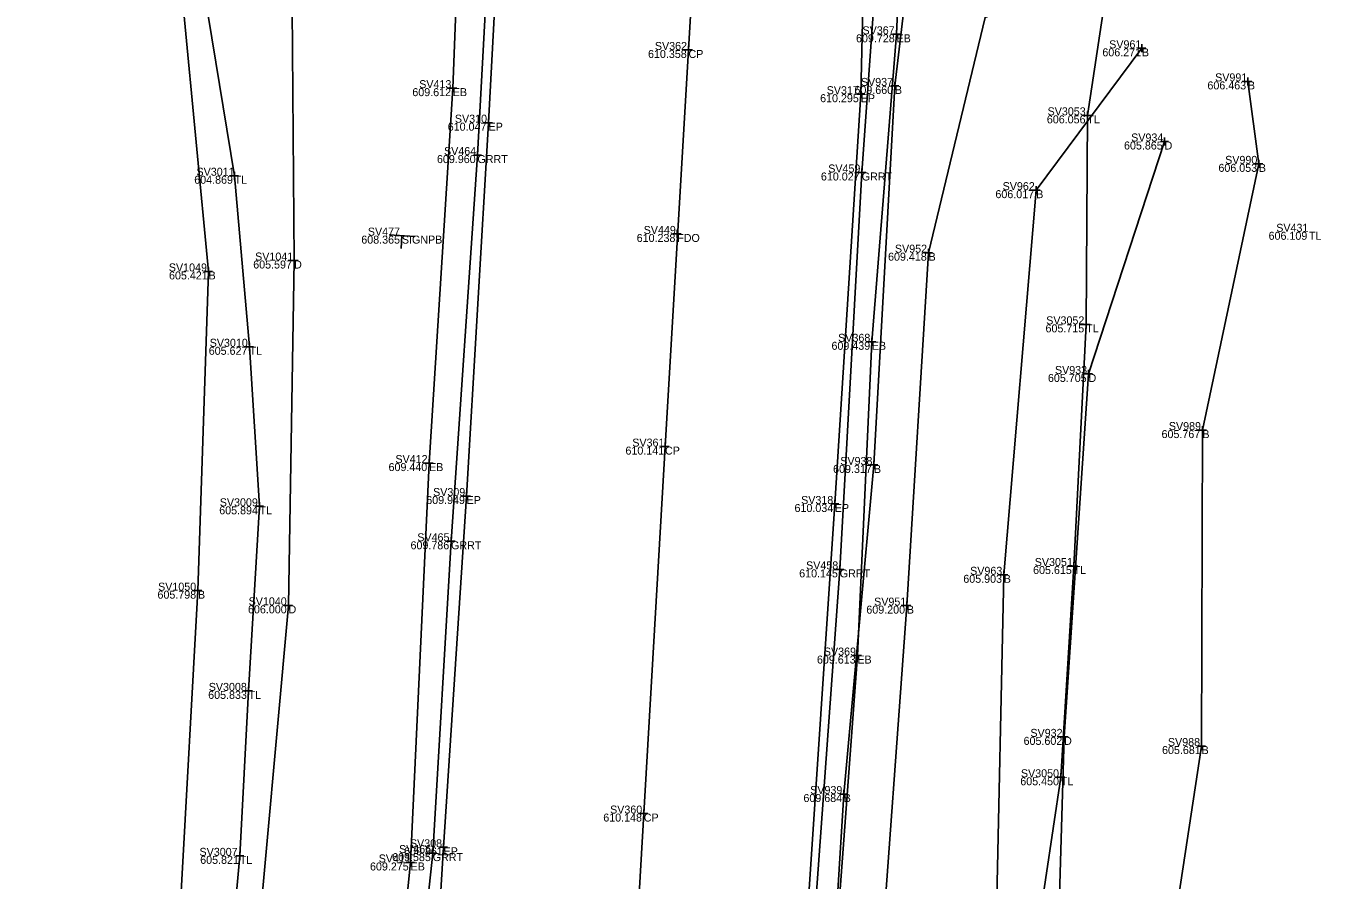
# Model space of a CAD drawing. Extents: x -2 to 1979875, y -2 to 232027.
# Drawn here: x 1978730.2 to 1978811.1, y 231153.6 to 231206.9 of the extents above; entities that cross this region are included whole.
import ezdxf

# ---------------------------------------------------------------- set-up
doc = ezdxf.new("R2010")
doc.units = 0
for name, color, linetype in [('_CIVIL_CONSTRUCTION', 7, 'Continuous'), ('DR_X_Ditch', 7, 'Continuous'), ('GE_P_Alignment', 7, 'Continuous'), ('GE_P_Alignment_1000_Curve_Data', 7, 'Continuous'), ('GE_P_Alignment_1000_Stations', 7, 'Continuous'), ('GE_P_Alignment_500_Curve_Data', 7, 'Continuous'), ('GE_X_Alignment', 7, 'Continuous'), ('GE_X_Alignment_1000_Curve_Data', 7, 'Continuous'), ('GE_X_Alignment_1000_Stations', 7, 'Continuous'), ('GE_X_Alignment_100_Curve_Data', 7, 'Continuous'), ('GE_X_Alignment_100_Stations', 7, 'Continuous'), ('GE_X_Alignment_500_Stations', 7, 'Continuous'), ('SC_Scratch1', 7, 'Continuous')]:
    doc.layers.add(name, color=color, linetype=linetype)

msp = doc.modelspace()

# ---------------------------------------------------------------- linework, layer by layer
at = {"layer": 'DR_X_Ditch'}
for points in [[(1978742.253, 231123.729), (1978744.469, 231147.505), (1978746.577, 231170.723), (1978746.925, 231192.27), (1978746.813, 231208.011), (1978745.79, 231216.793), (1978746.707, 231228.131), (1978745.697, 231237.66), (1978746.077, 231246.913)], [(1978769.61, 230735.533), (1978764.556, 230757.762), (1978761.888, 230780.52), (1978761.255, 230802.491), (1978762.758, 230825.129), (1978765.137, 230850.029), (1978768.569, 230875.252), (1978770.473, 230901.75), (1978772.394, 230926.88), (1978774.225, 230946.118), (1978776.188, 230970.1), (1978776.947, 230991.277), (1978778.808, 231013.722), (1978780.679, 231036.008), (1978780.852, 231047.689), (1978785.42, 231078.945), (1978790.697, 231097.051), (1978792.307, 231119.545), (1978794.395, 231141.248), (1978795.023, 231162.503), (1978796.552, 231185.182), (1978801.304, 231199.708)]]:
    msp.add_lwpolyline(points, dxfattribs=at)
at = {"layer": 'GE_P_Alignment'}
for points in [[(1978788.119, 231249.408), (1978786.943, 231224.352), (1978784.459, 231203.181), (1978783.148, 231179.495), (1978781.259, 231158.933), (1978779.831, 231135.814), (1978779.399, 231114.976), (1978780.51, 231101.208), (1978780.469, 231098.542), (1978778.925, 231080.086), (1978777.811, 231054.63), (1978776.389, 231030.876)], [(1978782.883, 231095.387), (1978784.018, 231105.569), (1978783.215, 231126.435), (1978783.474, 231146.96), (1978785.203, 231170.705), (1978786.559, 231192.76), (1978790.09, 231207.457), (1978796.435, 231210.256), (1978800.205, 231220.321), (1978799.997, 231235.458), (1978797.94, 231243.541), (1978796.315, 231248.532)], [(1978742.352, 231226.722), (1978740.039, 231207.756), (1978741.585, 231191.589), (1978740.923, 231171.641), (1978739.848, 231152.451), (1978736.877, 231135.037), (1978737.12, 231125.328)], [(1978799.886, 231205.531), (1978793.286, 231196.667), (1978791.255, 231172.632), (1978790.773, 231150.51), (1978789.185, 231127.08), (1978788.834, 231106.775), (1978786.415, 231093.172)], [(1978769.951, 230803.3), (1978770.804, 230818.73), (1978769.172, 230825.121), (1978771.54, 230837.858), (1978774.593, 230856.702), (1978777.309, 230875.323), (1978778.206, 230900.393), (1978780.194, 230917.861), (1978782.495, 230932.89), (1978782.493, 230947.115), (1978785.767, 230964.209), (1978787.856, 230986.866), (1978787.326, 231009.356), (1978787.324, 231025.342), (1978791.304, 231037.316), (1978793.971, 231062.015), (1978792.008, 231077.675), (1978794.496, 231103.739), (1978796.727, 231125.192), (1978800.775, 231143.28), (1978803.614, 231161.931), (1978803.663, 231181.675), (1978807.191, 231198.311), (1978806.504, 231203.464)]]:
    msp.add_lwpolyline(points, dxfattribs=at)
at = {"layer": 'GE_P_Alignment_1000_Curve_Data'}
for points in [[(1978791.661, 231060.333), (1978792.296, 231074.691), (1978791.754, 231088.963), (1978792.43, 231104.517), (1978792.032, 231117.838), (1978792.133, 231132.395), (1978792.905, 231147.152), (1978794.82, 231159.979), (1978795.624, 231173.18), (1978796.399, 231188.281), (1978796.48, 231201.342), (1978798.136, 231212.257), (1978799.055, 231226.533), (1978800.349, 231239.171), (1978800.253, 231250.204), (1978805.284, 231291.391)], [(1978737.693, 231077.945), (1978737.389, 231087.473), (1978737.815, 231097.725), (1978739.016, 231107.053), (1978740.421, 231120.833), (1978741.632, 231130.981), (1978742.549, 231144.249), (1978743.532, 231155.069), (1978744.086, 231165.377), (1978744.766, 231176.911), (1978744.147, 231186.88), (1978743.211, 231197.568), (1978741.558, 231207.59), (1978737.988, 231217.051), (1978732.124, 231225.954), (1978730.174, 231231.053), (1978733.125, 231254.651), (1978737.318, 231281.706)]]:
    msp.add_lwpolyline(points, dxfattribs=at)
at = {"layer": 'GE_P_Alignment_1000_Stations'}
for points in [[(1978761.115, 231248.004), (1978759.735, 231223.843), (1978758.381, 231198.86), (1978756.732, 231174.726), (1978755.587, 231155.241), (1978753.463, 231135.535), (1978751.71, 231124.03)], [(1978779.18, 231099.769), (1978777.975, 231123.065), (1978779.192, 231147.605), (1978781.012, 231172.97), (1978782.386, 231197.771), (1978784.253, 231223.721), (1978785.562, 231247.078)]]:
    msp.add_lwpolyline(points, dxfattribs=at)
at = {"layer": 'GE_P_Alignment_500_Curve_Data'}
for p, q in [((1978770.608, 231193.931), (1978771.108, 231193.931)), ((1978770.858, 231194.181), (1978770.858, 231193.681)), ((1978770.858, 231193.931), (1978770.858, 231193.931))]:
    msp.add_line(p, q, dxfattribs=at)
at = {"layer": 'GE_X_Alignment_1000_Curve_Data'}
msp.add_lwpolyline([(1978759.598, 230998.872), (1978761.121, 231023.464), (1978762.432, 231045.872), (1978763.634, 231067.205), (1978765.062, 231090.264), (1978766.176, 231112.831), (1978767.489, 231135.467), (1978768.77, 231157.711), (1978770.096, 231180.642), (1978771.565, 231205.428), (1978772.87, 231227.762), (1978774.351, 231252.439)], dxfattribs=at)
at = {"layer": 'GE_X_Alignment_1000_Stations'}
for points in [[(1978748.464, 231019.612), (1978749.988, 231043.472), (1978751.447, 231065.273), (1978752.63, 231084.658), (1978753.33, 231098.021), (1978753.711, 231111.371), (1978754.899, 231133.583), (1978756.265, 231155.604), (1978757.703, 231177.553), (1978759.075, 231200.883), (1978760.359, 231225.015), (1978761.255, 231242.617), (1978761.827, 231253.108)], [(1978785.568, 231251.827), (1978784.19, 231242.096), (1978782.784, 231222.648), (1978782.32, 231202.663), (1978780.702, 231177.057), (1978778.946, 231150.803), (1978777.805, 231126.797), (1978776.986, 231106.931), (1978775.705, 231085.257), (1978774.572, 231063.753), (1978773.517, 231041.76), (1978772.029, 231016.51), (1978770.7, 230994.507), (1978769.257, 230972.092), (1978767.73, 230948.595), (1978766.192, 230924.232), (1978764.603, 230899.039), (1978762.827, 230873.547), (1978761.273, 230848.668), (1978759.848, 230822.744), (1978759.345, 230799.915), (1978760.114, 230777.862), (1978762.938, 230755.551), (1978769.839, 230729.514)]]:
    msp.add_lwpolyline(points, dxfattribs=at)
at = {"layer": 'GE_X_Alignment_100_Curve_Data'}
for p, q in [((1978784.558, 231206.657), (1978784.558, 231206.157)), ((1978771.565, 231205.678), (1978771.565, 231205.178)), ((1978784.308, 231206.407), (1978784.808, 231206.407)), ((1978784.558, 231206.407), (1978784.558, 231206.407)), ((1978799.886, 231205.781), (1978799.886, 231205.281)), ((1978771.315, 231205.428), (1978771.815, 231205.428)), ((1978771.565, 231205.428), (1978771.565, 231205.428)), ((1978799.636, 231205.531), (1978800.136, 231205.531)), ((1978799.886, 231205.531), (1978799.886, 231205.531)), ((1978756.841, 231203.291), (1978756.841, 231202.791)), ((1978784.459, 231203.431), (1978784.459, 231202.931)), ((1978806.254, 231203.464), (1978806.754, 231203.464)), ((1978806.504, 231203.714), (1978806.504, 231203.214)), ((1978806.504, 231203.464), (1978806.504, 231203.464)), ((1978756.591, 231203.041), (1978757.091, 231203.041)), ((1978756.841, 231203.041), (1978756.841, 231203.041)), ((1978782.07, 231202.663), (1978782.57, 231202.663)), ((1978782.32, 231202.913), (1978782.32, 231202.413)), ((1978782.32, 231202.663), (1978782.32, 231202.663)), ((1978784.209, 231203.181), (1978784.709, 231203.181)), ((1978784.459, 231203.181), (1978784.459, 231203.181)), ((1978758.825, 231200.883), (1978759.325, 231200.883)), ((1978759.075, 231201.133), (1978759.075, 231200.633)), ((1978759.075, 231200.883), (1978759.075, 231200.883)), ((1978796.23, 231201.342), (1978796.73, 231201.342)), ((1978796.48, 231201.592), (1978796.48, 231201.092)), ((1978796.48, 231201.342), (1978796.48, 231201.342)), ((1978801.054, 231199.708), (1978801.554, 231199.708)), ((1978801.304, 231199.958), (1978801.304, 231199.458)), ((1978801.304, 231199.708), (1978801.304, 231199.708)), ((1978758.131, 231198.86), (1978758.631, 231198.86)), ((1978758.381, 231199.11), (1978758.381, 231198.61)), ((1978758.381, 231198.86), (1978758.381, 231198.86)), ((1978807.191, 231198.561), (1978807.191, 231198.061)), ((1978742.961, 231197.568), (1978743.461, 231197.568)), ((1978743.211, 231197.818), (1978743.211, 231197.318)), ((1978743.211, 231197.568), (1978743.211, 231197.568)), ((1978782.136, 231197.771), (1978782.636, 231197.771)), ((1978782.386, 231198.021), (1978782.386, 231197.521)), ((1978782.386, 231197.771), (1978782.386, 231197.771)), ((1978806.941, 231198.311), (1978807.441, 231198.311)), ((1978807.191, 231198.311), (1978807.191, 231198.311)), ((1978793.286, 231196.917), (1978793.286, 231196.417)), ((1978793.036, 231196.667), (1978793.536, 231196.667)), ((1978793.286, 231196.667), (1978793.286, 231196.667)), ((1978786.309, 231192.76), (1978786.809, 231192.76)), ((1978786.559, 231193.01), (1978786.559, 231192.51)), ((1978786.559, 231192.76), (1978786.559, 231192.76)), ((1978746.675, 231192.27), (1978747.175, 231192.27)), ((1978746.925, 231192.52), (1978746.925, 231192.02)), ((1978746.925, 231192.27), (1978746.925, 231192.27)), ((1978741.335, 231191.589), (1978741.835, 231191.589)), ((1978741.585, 231191.839), (1978741.585, 231191.339)), ((1978741.585, 231191.589), (1978741.585, 231191.589)), ((1978796.149, 231188.281), (1978796.649, 231188.281)), ((1978796.399, 231188.531), (1978796.399, 231188.031)), ((1978796.399, 231188.281), (1978796.399, 231188.281)), ((1978744.147, 231187.13), (1978744.147, 231186.63)), ((1978782.766, 231187.193), (1978783.266, 231187.193)), ((1978783.016, 231187.443), (1978783.016, 231186.943)), ((1978783.016, 231187.193), (1978783.016, 231187.193)), ((1978743.897, 231186.88), (1978744.397, 231186.88)), ((1978744.147, 231186.88), (1978744.147, 231186.88)), ((1978796.552, 231185.432), (1978796.552, 231184.932)), ((1978796.302, 231185.182), (1978796.802, 231185.182)), ((1978796.552, 231185.182), (1978796.552, 231185.182)), ((1978803.413, 231181.675), (1978803.913, 231181.675)), ((1978803.663, 231181.925), (1978803.663, 231181.425)), ((1978803.663, 231181.675), (1978803.663, 231181.675)), ((1978769.846, 231180.642), (1978770.346, 231180.642)), ((1978770.096, 231180.892), (1978770.096, 231180.392)), ((1978770.096, 231180.642), (1978770.096, 231180.642)), ((1978755.357, 231179.863), (1978755.357, 231179.363)), ((1978755.107, 231179.613), (1978755.607, 231179.613)), ((1978755.357, 231179.613), (1978755.357, 231179.613)), ((1978782.898, 231179.495), (1978783.398, 231179.495)), ((1978783.148, 231179.745), (1978783.148, 231179.245)), ((1978783.148, 231179.495), (1978783.148, 231179.495)), ((1978757.453, 231177.553), (1978757.953, 231177.553)), ((1978757.703, 231177.803), (1978757.703, 231177.303)), ((1978757.703, 231177.553), (1978757.703, 231177.553)), ((1978744.516, 231176.911), (1978745.016, 231176.911)), ((1978744.766, 231177.161), (1978744.766, 231176.661)), ((1978744.766, 231176.911), (1978744.766, 231176.911)), ((1978780.452, 231177.057), (1978780.952, 231177.057)), ((1978780.702, 231177.307), (1978780.702, 231176.807)), ((1978780.702, 231177.057), (1978780.702, 231177.057)), ((1978756.732, 231174.976), (1978756.732, 231174.476)), ((1978756.482, 231174.726), (1978756.982, 231174.726)), ((1978756.732, 231174.726), (1978756.732, 231174.726)), ((1978795.624, 231173.43), (1978795.624, 231172.93)), ((1978780.762, 231172.97), (1978781.262, 231172.97)), ((1978781.012, 231173.22), (1978781.012, 231172.72)), ((1978781.012, 231172.97), (1978781.012, 231172.97)), ((1978791.005, 231172.632), (1978791.505, 231172.632)), ((1978791.255, 231172.882), (1978791.255, 231172.382)), ((1978791.255, 231172.632), (1978791.255, 231172.632)), ((1978795.374, 231173.18), (1978795.874, 231173.18)), ((1978795.624, 231173.18), (1978795.624, 231173.18)), ((1978740.923, 231171.891), (1978740.923, 231171.391)), ((1978740.673, 231171.641), (1978741.173, 231171.641)), ((1978740.923, 231171.641), (1978740.923, 231171.641)), ((1978746.577, 231170.973), (1978746.577, 231170.473)), ((1978785.203, 231170.955), (1978785.203, 231170.455)), ((1978746.327, 231170.723), (1978746.827, 231170.723)), ((1978746.577, 231170.723), (1978746.577, 231170.723)), ((1978784.953, 231170.705), (1978785.453, 231170.705)), ((1978785.203, 231170.705), (1978785.203, 231170.705)), ((1978782.112, 231167.834), (1978782.112, 231167.334)), ((1978781.862, 231167.584), (1978782.362, 231167.584)), ((1978782.112, 231167.584), (1978782.112, 231167.584)), ((1978743.836, 231165.377), (1978744.336, 231165.377)), ((1978744.086, 231165.627), (1978744.086, 231165.127)), ((1978744.086, 231165.377), (1978744.086, 231165.377)), ((1978794.773, 231162.503), (1978795.273, 231162.503)), ((1978795.023, 231162.753), (1978795.023, 231162.253)), ((1978795.023, 231162.503), (1978795.023, 231162.503)), ((1978803.614, 231162.181), (1978803.614, 231161.681)), ((1978803.364, 231161.931), (1978803.864, 231161.931)), ((1978803.614, 231161.931), (1978803.614, 231161.931)), ((1978794.57, 231159.979), (1978795.07, 231159.979)), ((1978794.82, 231160.229), (1978794.82, 231159.729)), ((1978794.82, 231159.979), (1978794.82, 231159.979)), ((1978781.009, 231158.933), (1978781.509, 231158.933)), ((1978781.259, 231159.183), (1978781.259, 231158.683)), ((1978781.259, 231158.933), (1978781.259, 231158.933)), ((1978768.77, 231157.961), (1978768.77, 231157.461)), ((1978768.52, 231157.711), (1978769.02, 231157.711)), ((1978768.77, 231157.711), (1978768.77, 231157.711)), ((1978756.015, 231155.604), (1978756.515, 231155.604)), ((1978756.265, 231155.854), (1978756.265, 231155.354)), ((1978756.265, 231155.604), (1978756.265, 231155.604)), ((1978743.282, 231155.069), (1978743.782, 231155.069)), ((1978743.532, 231155.319), (1978743.532, 231154.819)), ((1978743.532, 231155.069), (1978743.532, 231155.069)), ((1978754.204, 231154.905), (1978754.204, 231154.405)), ((1978755.337, 231155.241), (1978755.837, 231155.241)), ((1978755.587, 231155.491), (1978755.587, 231154.991)), ((1978755.587, 231155.241), (1978755.587, 231155.241)), ((1978753.954, 231154.655), (1978754.454, 231154.655)), ((1978754.204, 231154.655), (1978754.204, 231154.655))]:
    msp.add_line(p, q, dxfattribs=at)
at = {"layer": 'GE_X_Alignment_500_Stations'}
for p, q in [((1978752.861, 231193.872), (1978754.459, 231193.78)), ((1978753.66, 231193.826), (1978753.614, 231193.027))]:
    msp.add_line(p, q, dxfattribs=at)
at = {"layer": 'SC_Scratch1'}
for points in [[(1978745.216, 230999.029), (1978746.767, 231023.392), (1978748.222, 231047.741), (1978749.82, 231072.495), (1978750.429, 231094.309), (1978750.937, 231113.218), (1978752.038, 231133.252), (1978754.204, 231154.655), (1978755.357, 231179.613), (1978756.841, 231203.041), (1978757.548, 231221.462), (1978759.078, 231239.679), (1978759.58, 231251.031)], [(1978787.694, 231249.601), (1978785.48, 231226.833), (1978784.558, 231206.407), (1978783.016, 231187.193), (1978782.112, 231167.584), (1978780.51, 231145.937), (1978779.287, 231125.907), (1978778.425, 231108.773), (1978777.775, 231087.524), (1978776.748, 231064.782), (1978775.35, 231040.582), (1978774.462, 231016.281), (1978772.549, 230990.683), (1978771.051, 230965.635), (1978769.086, 230942.407), (1978767.324, 230917.989), (1978765.95, 230893.701), (1978764.896, 230870.53), (1978763.088, 230848.633), (1978761.583, 230826.273), (1978760.498, 230804.271), (1978761.5, 230780.247), (1978763.845, 230755.469), (1978770.352, 230731.454)]]:
    msp.add_lwpolyline(points, dxfattribs=at)

# ---------------------------------------------------------------- texts
at = {"layer": '_CIVIL_CONSTRUCTION'}
for s, p in [('609.728', (1978782.028, 231205.907)), ('610.358', (1978769.035, 231204.928)), ('606.271', (1978797.416, 231205.031)), ('606.463', (1978803.979, 231202.964)), ('609.612', (1978754.313, 231202.541)), ('610.295', (1978779.785, 231202.163)), ('609.660', (1978781.929, 231202.681)), ('610.047', (1978756.524, 231200.383)), ('606.056', (1978793.948, 231200.842)), ('605.865', (1978798.769, 231199.208)), ('609.960', (1978755.851, 231198.36)), ('604.869', (1978740.69, 231197.068)), ('610.027', (1978779.835, 231197.271)), ('606.053', (1978804.666, 231197.811)), ('606.017', (1978790.735, 231196.167)), ('608.365', (1978751.125, 231193.326)), ('610.238', (1978768.328, 231193.431)), ('606.109', (1978807.8, 231193.566)), ('609.418', (1978784.029, 231192.26)), ('605.597', (1978744.374, 231191.77)), ('605.421', (1978739.115, 231191.089)), ('605.715', (1978793.864, 231187.781)), ('609.439', (1978780.495, 231186.693)), ('605.627', (1978741.596, 231186.38)), ('605.705', (1978794.017, 231184.682)), ('605.767', (1978801.112, 231181.175)), ('610.141', (1978767.626, 231180.142)), ('609.440', (1978752.827, 231179.113)), ('609.317', (1978780.597, 231178.995)), ('609.949', (1978755.182, 231177.053)), ('605.894', (1978742.25, 231176.411)), ('610.034', (1978778.186, 231176.557)), ('609.786', (1978754.2, 231174.226)), ('610.145', (1978778.477, 231172.47)), ('605.903', (1978788.73, 231172.132)), ('605.615', (1978793.089, 231172.68)), ('605.798', (1978738.393, 231171.141)), ('606.000', (1978744.047, 231170.223)), ('609.200', (1978782.673, 231170.205)), ('609.613', (1978779.587, 231167.084)), ('605.833', (1978741.561, 231164.877)), ('605.602', (1978792.495, 231162.003)), ('605.681', (1978801.144, 231161.431)), ('605.450', (1978792.29, 231159.479)), ('609.684', (1978778.743, 231158.433)), ('610.148', (1978766.24, 231157.211)), ('609.861', (1978753.795, 231155.104)), ('605.821', (1978741.062, 231154.569)), ('609.585', (1978753.052, 231154.741)), ('609.275', (1978751.669, 231154.155))]:
    msp.add_text(s, height=0.5, dxfattribs=at).set_placement(p)
at = {"layer": 'GE_X_Alignment'}
for s, p in [('SV367', (1978782.433, 231206.407)), ('SV362', (1978769.464, 231205.428)), ('SV961', (1978797.843, 231205.531)), ('SV413', (1978754.743, 231203.041)), ('SV937', (1978782.334, 231203.181)), ('SV991', (1978804.461, 231203.464)), ('SV317', (1978780.195, 231202.663)), ('SV3053', (1978793.994, 231201.342)), ('SV310', (1978756.971, 231200.883)), ('SV934', (1978799.215, 231199.708)), ('SV464', (1978756.292, 231198.86)), ('SV990', (1978805.087, 231198.311)), ('SV3011', (1978740.831, 231197.568)), ('SV459', (1978780.292, 231197.771)), ('SV962', (1978791.185, 231196.667)), ('SV477', (1978751.535, 231193.826)), ('SV449', (1978768.764, 231193.931)), ('SV431', (1978808.278, 231194.066)), ('SV1041', (1978744.493, 231192.27)), ('SV952', (1978784.458, 231192.76)), ('SV1049', (1978739.103, 231191.589)), ('SV3052', (1978793.909, 231188.281)), ('SV3010', (1978741.655, 231186.88)), ('SV368', (1978780.913, 231187.193)), ('SV933', (1978794.454, 231185.182)), ('SV989', (1978801.569, 231181.675)), ('SV361', (1978768.053, 231180.642)), ('SV412', (1978753.256, 231179.613)), ('SV938', (1978781.045, 231179.495)), ('SV3009', (1978742.284, 231176.911)), ('SV309', (1978755.609, 231177.553)), ('SV318', (1978778.599, 231177.057)), ('SV465', (1978754.623, 231174.726)), ('SV458', (1978778.909, 231172.97)), ('SV3051', (1978793.192, 231173.18)), ('SV963', (1978789.157, 231172.632)), ('SV1050', (1978738.431, 231171.641)), ('SV1040', (1978744.085, 231170.723)), ('SV951', (1978783.16, 231170.705)), ('SV369', (1978780.018, 231167.584)), ('SV3008', (1978741.595, 231165.377)), ('SV932', (1978792.922, 231162.503)), ('SV988', (1978801.511, 231161.931)), ('SV3050', (1978792.328, 231159.979)), ('SV939', (1978779.165, 231158.933)), ('SV360', (1978766.666, 231157.711)), ('SV3007', (1978741.019, 231155.069)), ('SV466', (1978753.482, 231155.241)), ('SV308', (1978754.162, 231155.604)), ('SV411', (1978752.212, 231154.655))]:
    msp.add_text(s, height=0.5, dxfattribs=at).set_placement(p)
at = {"layer": 'GE_X_Alignment_100_Stations'}
for s, p in [('EB', (1978784.558, 231205.907)), ('CP', (1978771.565, 231204.928)), ('B', (1978799.886, 231205.031)), ('B', (1978806.504, 231202.964)), ('EB', (1978756.841, 231202.541)), ('EP', (1978782.32, 231202.163)), ('B', (1978784.459, 231202.681)), ('EP', (1978759.075, 231200.383)), ('TL', (1978796.48, 231200.842)), ('D', (1978801.304, 231199.208)), ('GRRT', (1978758.381, 231198.36)), ('TL', (1978743.211, 231197.068)), ('GRRT', (1978782.386, 231197.271)), ('B', (1978807.191, 231197.811)), ('B', (1978793.286, 231196.167)), ('SIGNPB', (1978753.66, 231193.326)), ('FDO', (1978770.858, 231193.431)), ('TL', (1978810.321, 231193.566)), ('B', (1978786.559, 231192.26)), ('D', (1978746.925, 231191.77)), ('B', (1978741.585, 231191.089)), ('TL', (1978796.399, 231187.781)), ('EB', (1978783.016, 231186.693)), ('TL', (1978744.147, 231186.38)), ('D', (1978796.552, 231184.682)), ('B', (1978803.663, 231181.175)), ('CP', (1978770.096, 231180.142)), ('EB', (1978755.357, 231179.113)), ('B', (1978783.148, 231178.995)), ('EP', (1978757.703, 231177.053)), ('TL', (1978744.766, 231176.411)), ('EP', (1978780.702, 231176.557)), ('GRRT', (1978756.732, 231174.226)), ('GRRT', (1978781.012, 231172.47)), ('B', (1978791.255, 231172.132)), ('TL', (1978795.624, 231172.68)), ('B', (1978740.923, 231171.141)), ('D', (1978746.577, 231170.223)), ('B', (1978785.203, 231170.205)), ('EB', (1978782.112, 231167.084)), ('TL', (1978744.086, 231164.877)), ('D', (1978795.023, 231162.003)), ('B', (1978803.614, 231161.431)), ('TL', (1978794.82, 231159.479)), ('B', (1978781.259, 231158.433)), ('CP', (1978768.77, 231157.211)), ('EP', (1978756.265, 231155.104)), ('TL', (1978743.532, 231154.569)), ('GRRT', (1978755.587, 231154.741)), ('EB', (1978754.204, 231154.155))]:
    msp.add_text(s, height=0.5, dxfattribs=at).set_placement(p)

doc.saveas('drawing.dxf')
